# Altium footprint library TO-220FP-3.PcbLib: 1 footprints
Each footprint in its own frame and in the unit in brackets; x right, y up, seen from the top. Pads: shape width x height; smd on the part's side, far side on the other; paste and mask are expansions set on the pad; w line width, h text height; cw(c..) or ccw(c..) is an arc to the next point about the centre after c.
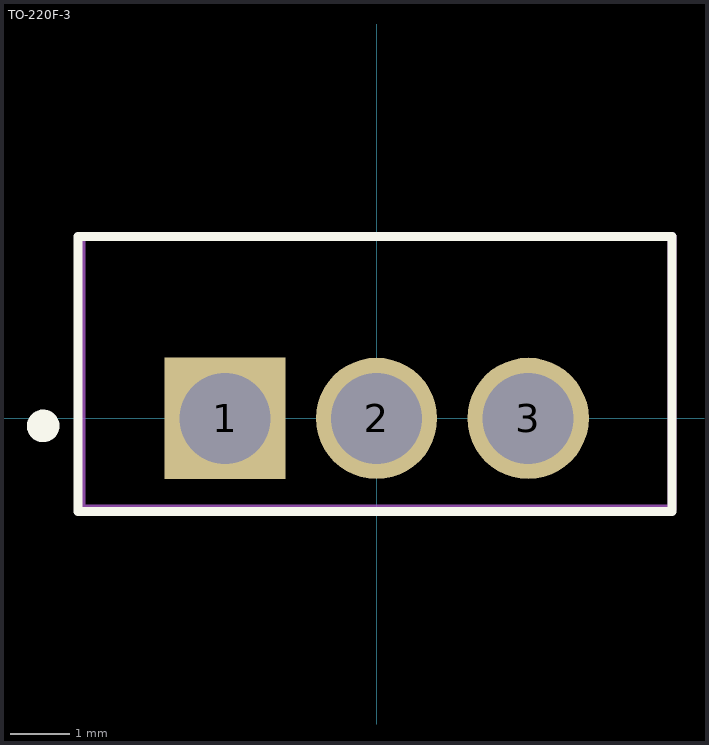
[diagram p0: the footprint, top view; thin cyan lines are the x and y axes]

## TO-220F-3 [mil]
pads (3):
  rect 80x80 hole 60: 1(-100,0)
  round 80 hole 60: 2(0,0) 3(100,0)
Top Overlay:
  circle w11.81: c-220,-5 r4.84
  lines w6: -196.97,-61.48 -196.97,120 195,120 195,-61.48 -196.97,-61.48
Mechanical 15:
  lines w6: -195,-60 195,-60 195,120 -195,120 -195,-60
3D body "TO-220F-3.STEP": height 782.28, standoff -353.54, extent -200.24,-64.38 199,120.66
